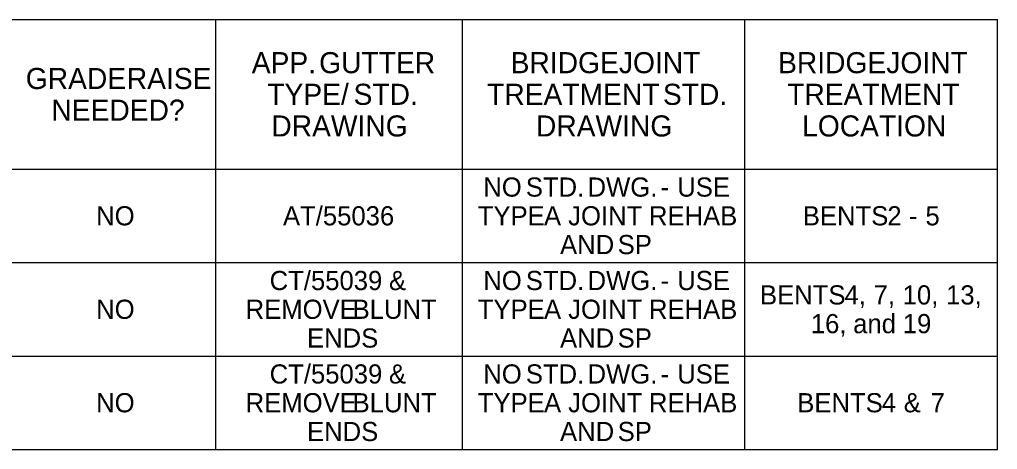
# Model space of a CAD drawing. Extents: x 16 to 1228740, y 11 to 152440.
# Drawn here: x 17.432 to 17.977, y 11.176 to 11.416 of the extents above; entities that cross this region are included whole.
import ezdxf

# ---------------------------------------------------------------- set-up
doc = ezdxf.new("R2010")
doc.units = 0
doc.layers.add('B_Text', color=7, linetype='Continuous')

msp = doc.modelspace()

# ---------------------------------------------------------------- linework, layer by layer
at = {"layer": 'B_Text'}
for p, q in [((16.24888, 11.41567), (17.9766, 11.41567)), ((17.54155, 11.17628), (17.54155, 11.41567)), ((17.67893, 11.17628), (17.67893, 11.41567)), ((17.83609, 11.17628), (17.83609, 11.41567)), ((17.9766, 11.17628), (17.9766, 11.41567)), ((16.24888, 11.3324), (17.9766, 11.3324)), ((16.24888, 11.28036), (17.9766, 11.28036)), ((16.24888, 11.22832), (17.9766, 11.22832)), ((16.24888, 11.17628), (17.9766, 11.17628))]:
    msp.add_line(p, q, dxfattribs=at)

# ---------------------------------------------------------------- texts
for s, height, p in [('APP.', 0.011742, (17.5616, 11.38578)), (' GUTTER', 0.011742, (17.59473, 11.38578)), ('BRIDGE', 0.011742, (17.70566, 11.38578)), (' JOINT', 0.011742, (17.76155, 11.38578)), ('BRIDGE', 0.011742, (17.8545, 11.38578)), (' JOINT', 0.011742, (17.91038, 11.38578)), ('GRADE', 0.011742, (17.43581, 11.37697)), (' RAISE', 0.011742, (17.48768, 11.37697)), ('TYPE/', 0.011742, (17.57022, 11.36816)), (' STD.', 0.011742, (17.61387, 11.36816)), ('TREATMENT', 0.011742, (17.69257, 11.36816)), (' STD.', 0.011742, (17.78606, 11.36816)), ('TREATMENT', 0.011742, (17.8596, 11.36816)), ('NEEDED?', 0.011742, (17.45006, 11.35936)), ('DRAWING', 0.011742, (17.57248, 11.35055)), ('DRAWING', 0.011742, (17.71975, 11.35055)), ('LOCATION', 0.011742, (17.86789, 11.35055)), ('NO', 0.010675, (17.69044, 11.31706)), (' STD.', 0.010675, (17.71015, 11.31706)), (' DWG.', 0.010675, (17.74451, 11.31706)), (' USE', 0.010675, (17.79443, 11.31706)), (' -', 0.010675, (17.78516, 11.31706)), ('NO', 0.010675, (17.47497, 11.30105)), ('AT/55036', 0.010675, (17.57896, 11.30105)), ('TYPE', 0.010675, (17.68738, 11.30105)), (' A', 0.010675, (17.72027, 11.30105)), (' JOINT', 0.010675, (17.73373, 11.30105)), (' REHAB', 0.010675, (17.77867, 11.30105)), ('BENTS', 0.010675, (17.86828, 11.30105)), (' 2', 0.010675, (17.91135, 11.30105)), (' 5', 0.010675, (17.93257, 11.30105)), (' -', 0.010675, (17.9233, 11.30105)), ('AND', 0.010675, (17.73316, 11.28503)), (' SP', 0.010675, (17.76127, 11.28503)), ('CT/55039', 0.010675, (17.57154, 11.26502)), (' &', 0.010675, (17.63399, 11.26502)), ('NO', 0.010675, (17.69044, 11.26502)), (' STD.', 0.010675, (17.71015, 11.26502)), (' DWG.', 0.010675, (17.74451, 11.26502)), (' USE', 0.010675, (17.79443, 11.26502)), (' -', 0.010675, (17.78516, 11.26502)), ('BENTS', 0.010675, (17.84444, 11.25701)), (' 4,', 0.010675, (17.88751, 11.25701)), (' 7,', 0.010675, (17.90369, 11.25701)), (' 10,', 0.010675, (17.91987, 11.25701)), (' 13,', 0.010675, (17.94405, 11.25701)), ('NO', 0.010675, (17.47497, 11.24901)), ('REMOVE', 0.010675, (17.55818, 11.24901)), (' BLUNT', 0.010675, (17.61375, 11.24901)), ('TYPE', 0.010675, (17.68738, 11.24901)), (' A', 0.010675, (17.72027, 11.24901)), (' JOINT', 0.010675, (17.73373, 11.24901)), (' REHAB', 0.010675, (17.77867, 11.24901)), ('16,', 0.010675, (17.87274, 11.241)), (' and', 0.010675, (17.89234, 11.241)), (' 19', 0.010675, (17.91995, 11.241)), ('ENDS', 0.010675, (17.59234, 11.23299)), ('AND', 0.010675, (17.73316, 11.23299)), (' SP', 0.010675, (17.76127, 11.23299)), ('CT/55039', 0.010675, (17.57154, 11.21298)), (' &', 0.010675, (17.63399, 11.21298)), ('NO', 0.010675, (17.69044, 11.21298)), (' STD.', 0.010675, (17.71015, 11.21298)), (' DWG.', 0.010675, (17.74451, 11.21298)), (' USE', 0.010675, (17.79443, 11.21298)), (' -', 0.010675, (17.78516, 11.21298)), ('NO', 0.010675, (17.47497, 11.19697)), ('REMOVE', 0.010675, (17.55818, 11.19697)), (' BLUNT', 0.010675, (17.61375, 11.19697)), ('TYPE', 0.010675, (17.68738, 11.19697)), (' A', 0.010675, (17.72027, 11.19697)), (' JOINT', 0.010675, (17.73373, 11.19697)), (' REHAB', 0.010675, (17.77867, 11.19697)), ('BENTS', 0.010675, (17.86519, 11.19697)), (' 4', 0.010675, (17.90826, 11.19697)), (' &', 0.010675, (17.92049, 11.19697)), (' 7', 0.010675, (17.93543, 11.19697)), ('ENDS', 0.010675, (17.59234, 11.18095)), ('AND', 0.010675, (17.73316, 11.18095)), (' SP', 0.010675, (17.76127, 11.18095))]:
    msp.add_text(s, height=height, dxfattribs=at).set_placement(p)

doc.saveas('drawing.dxf')
